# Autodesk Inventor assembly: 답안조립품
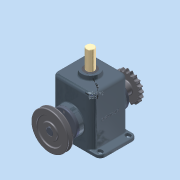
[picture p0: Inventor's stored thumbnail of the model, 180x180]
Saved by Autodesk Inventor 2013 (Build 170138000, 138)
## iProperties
Created: 2015-03
Part Number: 답안조립품
Document SubType Name: Assembly
Designer: Administrator
Mass: 8579.12 g
Surface Area: 4386.42 cm^2
Volume: 1982.52 cm^3
Density: 4.32738 g/cm^3
Author: Administrator
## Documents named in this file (15)
- C:\Documents and Settings\Administrator\바탕 화면\350305V1030\답안조립품.iam
- C:\Documents and Settings\Administrator\바탕 화면\350305V1030\본체.ipt
- C:\Documents and Settings\Administrator\바탕 화면\350305V1030\베어링 6205.ipt
- C:\Documents and Settings\Administrator\바탕 화면\350305V1030\커버.ipt
- C:\Documents and Settings\Administrator\바탕 화면\350305V1030\M4x0.5.ipt
- C:\Documents and Settings\Administrator\바탕 화면\350305V1030\편심축.ipt
- C:\Documents and Settings\Administrator\바탕 화면\350305V1030\오일실.ipt
- C:\Documents and Settings\Administrator\바탕 화면\350305V1030\키 8x8.ipt
- C:\Documents and Settings\Administrator\바탕 화면\350305V1030\체인 스프로킷.ipt
- C:\Documents and Settings\Administrator\바탕 화면\350305V1030\멈춤나사 M5x0.5.ipt
- C:\Documents and Settings\Administrator\바탕 화면\350305V1030\V-벨트풀리.ipt
- C:\Documents and Settings\Administrator\바탕 화면\350305V1030\멈춤링.ipt
- C:\Documents and Settings\Administrator\바탕 화면\350305V1030\부시.ipt
- C:\Documents and Settings\Administrator\바탕 화면\350305V1030\슬라이드.ipt
- C:\Documents and Settings\Administrator\바탕 화면\350305V1030\7 - 가변스프링.ipt
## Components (9 placed, 4 different names)
1. M4x0.5:1
2. M4x0.5:2
3. M4x0.5:3
4. M4x0.5:4
5. M4x0.5:5
6. M4x0.5:6
7. 5-체인 스프로킷:1 — 각도:2, 플러쉬:1
8. V-벨트풀리:1 — 각도:4, 플러쉬:2
9. 7 - 가변스프링:1
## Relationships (4: Angle 2, Flush 2)
- 각도:2 [Angle]: 5-체인 스프로킷:1
- 플러쉬:1 [Flush]: 5-체인 스프로킷:1
- 각도:4 [Angle]: V-벨트풀리:1
- 플러쉬:2 [Flush]: V-벨트풀리:1
